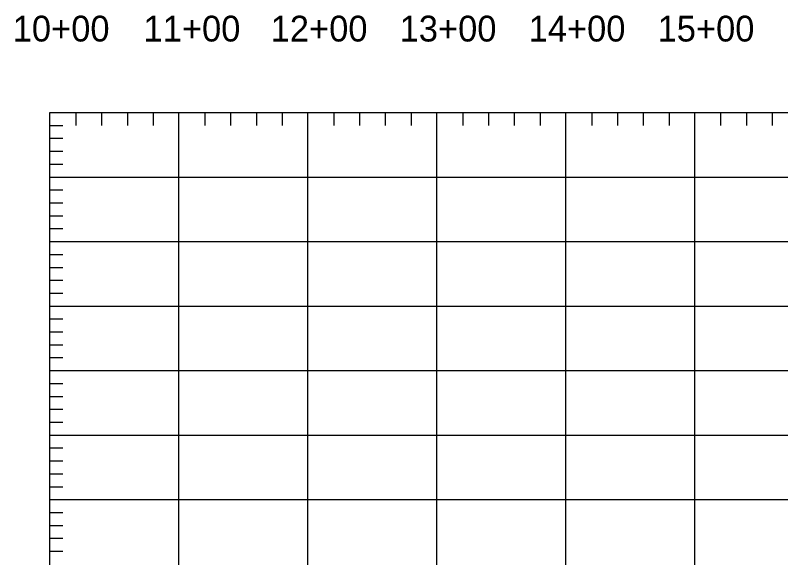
# Model space of a CAD drawing. Extents: x 704797 to 712284, y 374940 to 376945.
# Drawn here: x 708107 to 708700, y 375580 to 376001 of the extents above; entities that cross this region are included whole.
import ezdxf

# ---------------------------------------------------------------- set-up
doc = ezdxf.new("R2010")
doc.units = 0
doc.layers.add('61', color=7, linetype='Continuous')

msp = doc.modelspace()

# ---------------------------------------------------------------- linework, layer by layer
at = {"layer": '61'}
for p, q in [((708133.69, 375925.47), (712133.69, 375925.47)), ((708133.69, 375225.47), (708133.69, 375925.47)), ((708153.69, 375925.47), (708153.69, 375915.47)), ((708173.69, 375925.47), (708173.69, 375915.47)), ((708193.69, 375925.47), (708193.69, 375915.47)), ((708213.69, 375925.47), (708213.69, 375915.47)), ((708233.69, 375225.47), (708233.69, 375925.47)), ((708253.69, 375925.47), (708253.69, 375915.47)), ((708273.69, 375925.47), (708273.69, 375915.47)), ((708293.69, 375925.47), (708293.69, 375915.47)), ((708313.69, 375925.47), (708313.69, 375915.47)), ((708333.69, 375225.47), (708333.69, 375925.47)), ((708353.69, 375925.47), (708353.69, 375915.47)), ((708373.69, 375925.47), (708373.69, 375915.47)), ((708393.69, 375925.47), (708393.69, 375915.47)), ((708413.69, 375925.47), (708413.69, 375915.47)), ((708433.69, 375225.47), (708433.69, 375925.47)), ((708453.69, 375925.47), (708453.69, 375915.47)), ((708473.69, 375925.47), (708473.69, 375915.47)), ((708493.69, 375925.47), (708493.69, 375915.47)), ((708513.69, 375925.47), (708513.69, 375915.47)), ((708533.69, 375225.47), (708533.69, 375925.47)), ((708553.69, 375925.47), (708553.69, 375915.47)), ((708573.69, 375925.47), (708573.69, 375915.47)), ((708593.69, 375925.47), (708593.69, 375915.47)), ((708613.69, 375925.47), (708613.69, 375915.47)), ((708633.69, 375225.47), (708633.69, 375925.47)), ((708653.69, 375925.47), (708653.69, 375915.47)), ((708673.69, 375925.47), (708673.69, 375915.47)), ((708693.69, 375925.47), (708693.69, 375915.47)), ((708133.69, 375915.47), (708143.69, 375915.47)), ((708133.69, 375905.47), (708143.69, 375905.47)), ((708133.69, 375895.47), (708143.69, 375895.47)), ((708133.69, 375885.47), (708143.69, 375885.47)), ((708133.69, 375875.47), (712133.69, 375875.47)), ((708133.69, 375865.47), (708143.69, 375865.47)), ((708133.69, 375855.47), (708143.69, 375855.47)), ((708133.69, 375845.47), (708143.69, 375845.47)), ((708133.69, 375835.47), (708143.69, 375835.47)), ((708133.69, 375825.47), (712133.69, 375825.47)), ((708133.69, 375815.47), (708143.69, 375815.47)), ((708133.69, 375805.47), (708143.69, 375805.47)), ((708133.69, 375795.47), (708143.69, 375795.47)), ((708133.69, 375785.47), (708143.69, 375785.47)), ((708133.69, 375775.47), (712133.69, 375775.47)), ((708133.69, 375765.47), (708143.69, 375765.47)), ((708133.69, 375755.47), (708143.69, 375755.47)), ((708133.69, 375745.47), (708143.69, 375745.47)), ((708133.69, 375735.47), (708143.69, 375735.47)), ((708133.69, 375725.47), (712133.69, 375725.47)), ((708133.69, 375715.47), (708143.69, 375715.47)), ((708133.69, 375705.47), (708143.69, 375705.47)), ((708133.69, 375695.47), (708143.69, 375695.47)), ((708133.69, 375685.47), (708143.69, 375685.47)), ((708133.69, 375675.47), (712133.69, 375675.47)), ((708133.69, 375665.47), (708143.69, 375665.47)), ((708133.69, 375655.47), (708143.69, 375655.47)), ((708133.69, 375645.47), (708143.69, 375645.47)), ((708133.69, 375635.47), (708143.69, 375635.47)), ((708133.69, 375625.47), (712133.69, 375625.47)), ((708133.69, 375615.47), (708143.69, 375615.47)), ((708133.69, 375605.47), (708143.69, 375605.47)), ((708133.69, 375595.47), (708143.69, 375595.47)), ((708133.69, 375585.47), (708143.69, 375585.47))]:
    msp.add_line(p, q, dxfattribs=at)

# ---------------------------------------------------------------- texts
for s, p in [('10+00', (708104.77, 375980.47)), ('11+00', (708206.21, 375980.47)), ('12+00', (708304.77, 375980.47)), ('13+00', (708404.77, 375980.47)), ('14+00', (708504.77, 375980.47)), ('15+00', (708604.77, 375980.47))]:
    msp.add_text(s, height=20, dxfattribs=at).set_placement(p)

doc.saveas('drawing.dxf')
